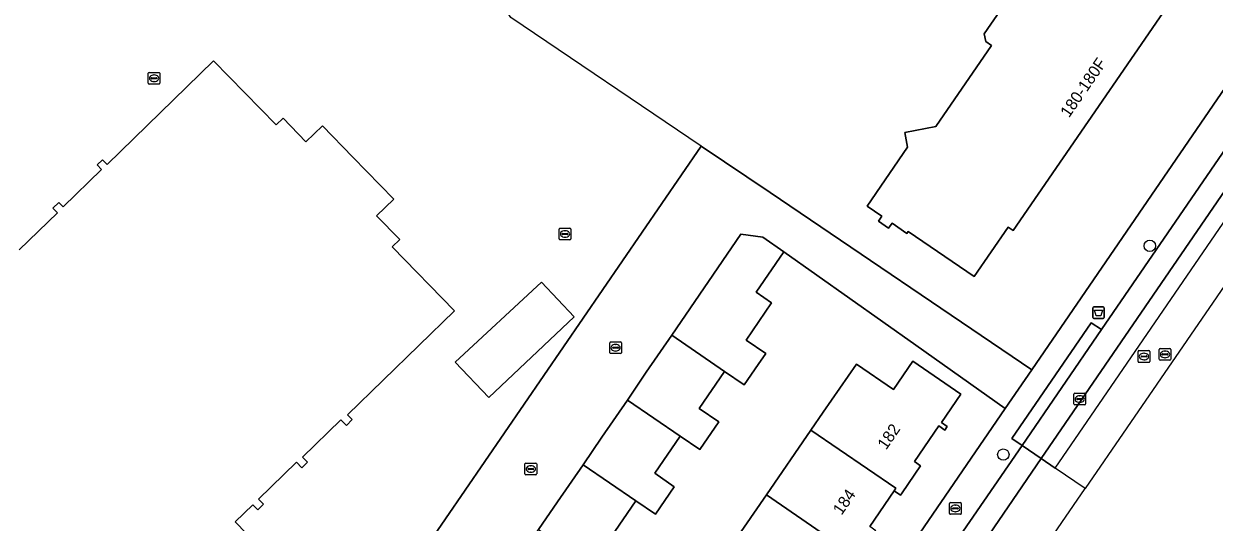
# Model space of a CAD drawing. Extents: x 159664 to 160323, y 385312 to 386115.
# Drawn here: x 160092.1 to 160193.9, y 385542.9 to 385585.5 of the extents above; entities that cross this region are included whole.
import ezdxf

# ---------------------------------------------------------------- set-up
doc = ezdxf.new("R2010")
doc.units = 0
for name, color, linetype in [('IMGEO_Afvalbak', 7, 'Continuous'), ('IMGEO_Boom', 7, 'Continuous'), ('IMGEO_Brandkraan', 7, 'Continuous'), ('IMGEO_Erf', 7, 'Continuous'), ('IMGEO_Hek', 7, 'Continuous'), ('IMGEO_Kolk', 7, 'Continuous'), ('IMGEO_Muur', 7, 'Continuous'), ('IMGEO_Pand', 7, 'Continuous'), ('IMGEO_Pand_nummerreeks', 7, 'Continuous'), ('IMGEO_Parkeervlak_open', 7, 'Continuous'), ('IMGEO_Rijbaan_lokaal_gesloten', 7, 'Continuous'), ('IMGEO_Rijbaan_lokaal_open', 7, 'Continuous'), ('IMGEO_Rioolput', 7, 'Continuous'), ('IMGEO_Voetpad_open', 7, 'Continuous')]:
    doc.layers.add(name, color=color, linetype=linetype)

msp = doc.modelspace()

# ---------------------------------------------------------------- linework, layer by layer
at = {"layer": 'IMGEO_Afvalbak'}
for p, q in [((160183.47, 385560.44), (160183.47, 385561.24)), ((160183.47, 385561.24), (160183.47, 385560.44)), ((160183.57, 385561.34), (160184.36, 385561.34)), ((160184.36, 385561.34), (160183.57, 385561.34)), ((160184.46, 385561.24), (160184.46, 385560.44)), ((160184.46, 385560.44), (160184.46, 385561.24)), ((160184.36, 385560.34), (160183.57, 385560.34)), ((160183.57, 385560.34), (160184.36, 385560.34))]:
    msp.add_line(p, q, dxfattribs=at)
msp.add_lwpolyline([(160183.61, 385561.05), (160184.32, 385561.05), (160184.17, 385560.58), (160183.76, 385560.58), (160183.61, 385561.05)], dxfattribs=at)
for centre, start, end in [((160183.57, 385561.24), 90, 180), ((160183.57, 385561.24), 90, 180), ((160184.36, 385561.24), 0, 90), ((160184.36, 385561.24), 360, 90), ((160183.57, 385560.44), 180, 270), ((160183.57, 385560.44), 180, 270), ((160184.36, 385560.44), 270, 0), ((160184.36, 385560.44), 270, 0)]:
    msp.add_arc(centre, 0.1, start, end, dxfattribs=at)
at = {"layer": 'IMGEO_Boom'}
for centre in [(160188.35, 385566.56), (160175.83, 385548.7)]:
    msp.add_circle(centre, 0.489, dxfattribs=at)
at = {"layer": 'IMGEO_Brandkraan'}
for p, q in [((160171.23, 385543.67), (160171.23, 385544.53)), ((160171.31, 385544.6), (160172.16, 385544.6)), ((160171.72, 385544.38), (160171.75, 385544.38)), ((160172.23, 385544.53), (160172.23, 385543.67)), ((160172.16, 385543.6), (160171.31, 385543.6)), ((160171.49, 385544.09), (160171.49, 385544.11)), ((160171.53, 385544.14), (160171.93, 385544.14)), ((160171.93, 385544.06), (160171.53, 385544.06)), ((160171.74, 385543.82), (160171.72, 385543.82)), ((160171.98, 385544.11), (160171.98, 385544.09))]:
    msp.add_line(p, q, dxfattribs=at)
for points in [[(160171.23, 385543.67), (160171.23, 385544.53)], [(160171.31, 385544.6), (160172.16, 385544.6)], [(160172.23, 385544.53), (160172.23, 385543.67)], [(160172.16, 385543.6), (160171.31, 385543.6)]]:
    msp.add_lwpolyline(points, dxfattribs=at)
for centre, radius, start, end in [((160171.31, 385544.52), 0.0765, 91.552, 178.448), ((160171.31, 385544.52), 0.0765, 91.552, 178.448), ((160172.16, 385544.52), 0.0765, 1.552, 88.448), ((160172.16, 385544.52), 0.0765, 1.552, 88.448), ((160171.31, 385543.67), 0.0765, 181.552, 268.448), ((160171.31, 385543.67), 0.0765, 181.552, 268.448), ((160171.53, 385544.1), 0.0403, 85.8775, 175.7526), ((160171.53, 385544.09), 0.0366, 178.938, 274.7102), ((160171.94, 385544.1), 0.0386, 1.7309, 96.639), ((160171.93, 385544.1), 0.043, 264.8664, 352.4533), ((160172.16, 385543.67), 0.0765, 271.552, 358.448), ((160172.16, 385543.67), 0.0765, 271.552, 358.448)]:
    msp.add_arc(centre, radius, start, end, dxfattribs=at)
for centre, major_axis, ratio, start_param, end_param in [((160171.72, 385544.1), (-0.387, 0.002), 0.722429, 4.712389, 7.853982), ((160171.74, 385544.1), (-0.39, 0.002), 0.717154, 1.570796, 4.712389)]:
    msp.add_ellipse(centre, major_axis=major_axis, ratio=ratio, start_param=start_param, end_param=end_param, dxfattribs=at)
at = {"layer": 'IMGEO_Erf'}
for points in [[(160193.45, 385592.29), (160176.67, 385567.86), (160176.24, 385568.16), (160173.33, 385563.92), (160167.71, 385567.78), (160167.59, 385567.61), (160166.32, 385568.48), (160166.03, 385568.07), (160165.15, 385568.67), (160165.45, 385569.1), (160164.2, 385569.96), (160167.65, 385574.99), (160167.42, 385576.26), (160170.06, 385576.75), (160174.82, 385583.68), (160174.33, 385584.02), (160174.2, 385584.68), (160175.6, 385586.72)], [(160126.47, 385540.77), (160150.01, 385575.09), (160155.89, 385571.12), (160178.27, 385555.96), (160202.57, 385591.48)], [(160091.73, 385566.22), (160094.98, 385569.39), (160094.6, 385569.78), (160095.11, 385570.27), (160095.48, 385569.89), (160098.76, 385573.08), (160098.39, 385573.47), (160098.84, 385573.91), (160099.23, 385573.51), (160108.33, 385582.37), (160113.67, 385576.89), (160114.27, 385577.47), (160116.23, 385575.46), (160117.63, 385576.82), (160120.24, 385574.14), (160123.73, 385570.55), (160122.26, 385569.12), (160124.24, 385567.09), (160123.6, 385566.47), (160128.92, 385561.01), (160119.79, 385552.11), (160120.19, 385551.7), (160119.68, 385551.2), (160119.22, 385551.67), (160115.93, 385548.48), (160116.36, 385548.04), (160115.89, 385547.57), (160115.41, 385548.05), (160112.17, 385544.9), (160112.61, 385544.45), (160112.11, 385543.97), (160111.68, 385544.41), (160110.18, 385542.95), (160111.14, 385541.96)], [(160149.71, 385514.25), (160176, 385552.63), (160168.35, 385558.05), (160157.07, 385566.03), (160154.72, 385562.6), (160156.03, 385561.69), (160153.85, 385558.5), (160155.52, 385557.36), (160154.89, 385556.42), (160153.68, 385554.67), (160152.01, 385555.82), (160149.84, 385552.64), (160151.51, 385551.5), (160149.89, 385549.13), (160148.22, 385550.28), (160146.04, 385547.1), (160147.71, 385545.95), (160146.1, 385543.6), (160144.43, 385544.74), (160142.26, 385541.57)], [(160151.77, 385539.72), (160155.58, 385545.25), (160159.38, 385550.78), (160160.44, 385552.32), (160163.27, 385556.44), (160166.45, 385554.27), (160168.09, 385556.68), (160172.21, 385553.87), (160170.55, 385551.44), (160171.04, 385551.11), (160170.83, 385550.8), (160170.31, 385551.15), (160168.23, 385548.1), (160168.76, 385547.74), (160167.19, 385545.43), (160167.05, 385545.23), (160166.49, 385545.6), (160164.41, 385542.54)]]:
    msp.add_lwpolyline(points, dxfattribs=at)
msp.add_lwpolyline([(160139.15, 385560.48), (160131.85, 385553.59), (160128.99, 385556.61), (160136.37, 385563.46)], close=True, dxfattribs=at)
at = {"layer": 'IMGEO_Hek'}
msp.add_lwpolyline([(160150.01, 385575.09), (160133.75, 385586.07), (160123.11, 385602.19), (160118.66, 385599.55), (160118.08, 385600.49)], dxfattribs=at)
at = {"layer": 'IMGEO_Kolk'}
for p, q in [((160142.19, 385557.41), (160142.19, 385558.27)), ((160142.27, 385558.34), (160143.12, 385558.34)), ((160142.45, 385557.83), (160142.45, 385557.85)), ((160142.49, 385557.88), (160142.89, 385557.88)), ((160142.89, 385557.8), (160142.49, 385557.8)), ((160142.68, 385558.12), (160142.71, 385558.12)), ((160142.94, 385557.85), (160142.94, 385557.83)), ((160143.19, 385558.27), (160143.19, 385557.41)), ((160143.12, 385557.34), (160142.27, 385557.34)), ((160142.7, 385557.56), (160142.68, 385557.56)), ((160181.86, 385553.03), (160181.86, 385553.88)), ((160181.94, 385553.96), (160182.79, 385553.96)), ((160182.16, 385553.5), (160182.56, 385553.5)), ((160182.35, 385553.73), (160182.37, 385553.73)), ((160182.86, 385553.88), (160182.86, 385553.03)), ((160182.79, 385552.95), (160181.94, 385552.95)), ((160182.12, 385553.45), (160182.12, 385553.46)), ((160182.56, 385553.41), (160182.16, 385553.41)), ((160182.37, 385553.18), (160182.35, 385553.18)), ((160182.6, 385553.46), (160182.6, 385553.45)), ((160134.95, 385547.05), (160134.95, 385547.9)), ((160135.02, 385547.98), (160135.87, 385547.98)), ((160135.2, 385547.47), (160135.2, 385547.48)), ((160135.64, 385547.43), (160135.24, 385547.43)), ((160135.25, 385547.52), (160135.64, 385547.52)), ((160135.43, 385547.75), (160135.46, 385547.75)), ((160135.69, 385547.48), (160135.69, 385547.47)), ((160135.95, 385547.9), (160135.95, 385547.05)), ((160135.87, 385546.97), (160135.02, 385546.97)), ((160135.46, 385547.2), (160135.43, 385547.2))]:
    msp.add_line(p, q, dxfattribs=at)
for points in [[(160142.19, 385557.41), (160142.19, 385558.27)], [(160142.27, 385558.34), (160143.12, 385558.34)], [(160143.19, 385558.27), (160143.19, 385557.41)], [(160143.12, 385557.34), (160142.27, 385557.34)], [(160181.86, 385553.03), (160181.86, 385553.88)], [(160181.94, 385553.96), (160182.79, 385553.96)], [(160182.86, 385553.88), (160182.86, 385553.03)], [(160182.79, 385552.95), (160181.94, 385552.95)], [(160134.95, 385547.05), (160134.95, 385547.9)], [(160135.02, 385547.98), (160135.87, 385547.98)], [(160135.95, 385547.9), (160135.95, 385547.05)], [(160135.87, 385546.97), (160135.02, 385546.97)]]:
    msp.add_lwpolyline(points, dxfattribs=at)
for centre, radius, start, end in [((160142.27, 385558.27), 0.0765, 91.552, 178.448), ((160142.27, 385558.27), 0.0765, 91.552, 178.448), ((160142.49, 385557.84), 0.0403, 85.8775, 175.7526), ((160142.49, 385557.83), 0.0366, 178.938, 274.7102), ((160142.9, 385557.85), 0.0386, 1.7309, 96.639), ((160142.89, 385557.84), 0.043, 264.8664, 352.4533), ((160143.12, 385558.27), 0.0765, 1.552, 88.448), ((160143.12, 385558.27), 0.0765, 1.552, 88.448), ((160142.27, 385557.42), 0.0765, 181.552, 268.448), ((160142.27, 385557.42), 0.0765, 181.552, 268.448), ((160143.12, 385557.42), 0.0765, 271.552, 358.448), ((160143.12, 385557.42), 0.0765, 271.552, 358.448), ((160181.94, 385553.88), 0.0765, 91.552, 178.448), ((160181.94, 385553.88), 0.0765, 91.552, 178.448), ((160182.16, 385553.46), 0.0403, 85.8775, 175.7526), ((160182.57, 385553.46), 0.0386, 1.7309, 96.639), ((160182.79, 385553.88), 0.0765, 1.552, 88.448), ((160182.79, 385553.88), 0.0765, 1.552, 88.448), ((160181.94, 385553.03), 0.0765, 181.552, 268.448), ((160181.94, 385553.03), 0.0765, 181.552, 268.448), ((160182.16, 385553.45), 0.0366, 178.938, 274.7102), ((160182.56, 385553.45), 0.043, 264.8664, 352.4533), ((160182.79, 385553.03), 0.0765, 271.552, 358.448), ((160182.79, 385553.03), 0.0765, 271.552, 358.448), ((160135.02, 385547.9), 0.0765, 91.552, 178.448), ((160135.02, 385547.9), 0.0765, 91.552, 178.448), ((160135.24, 385547.48), 0.0403, 85.8775, 175.7526), ((160135.24, 385547.47), 0.0366, 178.938, 274.7102), ((160135.65, 385547.48), 0.0386, 1.7309, 96.639), ((160135.65, 385547.47), 0.043, 264.8664, 352.4533), ((160135.87, 385547.9), 0.0765, 1.552, 88.448), ((160135.87, 385547.9), 0.0765, 1.552, 88.448), ((160135.02, 385547.05), 0.0765, 181.552, 268.448), ((160135.02, 385547.05), 0.0765, 181.552, 268.448), ((160135.87, 385547.05), 0.0765, 271.552, 358.448), ((160135.87, 385547.05), 0.0765, 271.552, 358.448)]:
    msp.add_arc(centre, radius, start, end, dxfattribs=at)
for centre, major_axis, ratio, start_param, end_param in [((160142.68, 385557.84), (-0.387, 0.002), 0.722429, 4.712389, 7.853982), ((160142.7, 385557.84), (-0.39, 0.002), 0.717154, 1.570796, 4.712389), ((160182.35, 385553.45), (-0.387, 0.002), 0.722429, 4.712389, 7.853982), ((160182.37, 385553.45), (-0.39, 0.002), 0.717154, 1.570796, 4.712389), ((160135.43, 385547.47), (-0.387, 0.002), 0.722429, 4.712389, 7.853982), ((160135.46, 385547.47), (-0.39, 0.002), 0.717154, 1.570796, 4.712389)]:
    msp.add_ellipse(centre, major_axis=major_axis, ratio=ratio, start_param=start_param, end_param=end_param, dxfattribs=at)
at = {"layer": 'IMGEO_Muur'}
msp.add_lwpolyline([(160168.35, 385558.05), (160157.07, 385566.03)], dxfattribs=at)
at = {"layer": 'IMGEO_Pand'}
for points in [[(160175.6, 385586.72), (160174.2, 385584.68), (160174.33, 385584.02), (160174.82, 385583.68), (160170.06, 385576.75), (160167.42, 385576.26), (160167.65, 385574.99), (160164.2, 385569.96), (160165.45, 385569.1), (160165.15, 385568.67), (160166.03, 385568.07), (160166.32, 385568.48), (160167.59, 385567.61), (160167.71, 385567.78), (160173.33, 385563.92), (160176.24, 385568.16), (160176.67, 385567.86), (160193.45, 385592.29)], [(160111.14, 385541.96), (160110.18, 385542.95), (160111.68, 385544.41), (160112.11, 385543.97), (160112.61, 385544.45), (160112.17, 385544.9), (160115.41, 385548.05), (160115.89, 385547.57), (160116.36, 385548.04), (160115.93, 385548.48), (160119.22, 385551.67), (160119.68, 385551.2), (160120.19, 385551.7), (160119.79, 385552.11), (160128.92, 385561.01), (160123.6, 385566.47), (160124.24, 385567.09), (160122.26, 385569.12), (160123.73, 385570.55), (160120.24, 385574.14), (160117.63, 385576.82), (160116.23, 385575.46), (160114.27, 385577.47), (160113.67, 385576.89), (160108.33, 385582.37), (160099.23, 385573.51), (160098.84, 385573.91), (160098.39, 385573.47), (160098.76, 385573.08), (160095.48, 385569.89), (160095.11, 385570.27), (160094.6, 385569.78), (160094.98, 385569.39), (160091.73, 385566.22)]]:
    msp.add_lwpolyline(points, dxfattribs=at)
for points in [[(160154.72, 385562.6), (160157.07, 385566.03), (160155.28, 385567.3), (160153.4, 385567.55), (160147.49, 385558.91), (160152.01, 385555.82), (160153.68, 385554.67), (160154.89, 385556.42), (160155.52, 385557.36), (160153.85, 385558.5), (160156.03, 385561.69)], [(160139.15, 385560.48), (160136.37, 385563.46), (160128.99, 385556.61), (160131.85, 385553.59)], [(160152.01, 385555.82), (160147.49, 385558.91), (160145.32, 385555.74), (160143.7, 385553.37), (160148.22, 385550.28), (160149.89, 385549.13), (160151.51, 385551.5), (160149.84, 385552.64)], [(160172.21, 385553.87), (160168.09, 385556.68), (160166.45, 385554.27), (160163.27, 385556.44), (160160.44, 385552.32), (160159.38, 385550.78), (160166.64, 385545.82), (160166.49, 385545.6), (160167.05, 385545.23), (160167.19, 385545.43), (160168.76, 385547.74), (160168.23, 385548.1), (160170.31, 385551.15), (160170.83, 385550.8), (160171.04, 385551.11), (160170.55, 385551.44)], [(160148.22, 385550.28), (160143.7, 385553.37), (160141.52, 385550.19), (160139.91, 385547.83), (160144.43, 385544.74), (160146.1, 385543.6), (160147.71, 385545.95), (160146.04, 385547.1)], [(160159.38, 385550.78), (160155.58, 385545.25), (160162.84, 385540.28), (160162.72, 385540.1), (160163.26, 385539.73), (160163.39, 385539.91), (160164.93, 385542.18), (160164.41, 385542.54), (160166.49, 385545.6), (160166.64, 385545.82)], [(160144.43, 385544.74), (160139.91, 385547.83), (160137.74, 385544.67), (160136.11, 385542.29), (160140.64, 385539.2), (160142.31, 385538.06), (160143.93, 385540.42), (160142.26, 385541.57)], [(160155.58, 385545.25), (160151.77, 385539.72), (160159.09, 385534.72), (160158.98, 385534.56), (160159.51, 385534.2), (160159.62, 385534.35), (160161.18, 385536.64), (160160.62, 385537.02), (160162.72, 385540.1), (160162.84, 385540.28)]]:
    msp.add_lwpolyline(points, close=True, dxfattribs=at)
at = {"layer": 'IMGEO_Parkeervlak_open'}
for points in [[(160179.07, 385548.37), (160214.31, 385599.82)], [(160203.92, 385588.15), (160184.21, 385559.4)], [(160184.21, 385559.4), (160177.43, 385549.49)], [(160177.43, 385549.49), (160179.07, 385548.37)]]:
    msp.add_lwpolyline(points, dxfattribs=at)
msp.add_lwpolyline([(160171.77, 385541.23), (160173.43, 385540.1), (160179.07, 385548.37), (160177.43, 385549.49)], close=True, dxfattribs=at)
at = {"layer": 'IMGEO_Rijbaan_lokaal_gesloten'}
for points in [[(160232.59, 385623.94), (160231.37, 385624.76), (160215.29, 385601.23), (160215.23, 385601.14), (160214.31, 385599.82), (160179.07, 385548.37), (160180.26, 385547.55)], [(160182.82, 385545.79), (160180.26, 385547.55), (160232.59, 385623.94), (160235.22, 385622.16), (160233.16, 385619.15), (160186.38, 385550.98)]]:
    msp.add_lwpolyline(points, close=True, dxfattribs=at)
at = {"layer": 'IMGEO_Rijbaan_lokaal_open'}
for points in [[(160139.91, 385547.83), (160141.52, 385550.19), (160143.7, 385553.37), (160145.32, 385555.74), (160147.49, 385558.91), (160153.4, 385567.55), (160155.28, 385567.3), (160157.07, 385566.03), (160168.35, 385558.05), (160176, 385552.63), (160177.7, 385555.13), (160178.27, 385555.96), (160155.89, 385571.12), (160150.01, 385575.09), (160126.47, 385540.77), (160132.33, 385536.76), (160133.93, 385539.11), (160136.11, 385542.29), (160137.74, 385544.67)], [(160177.15, 385537.53), (160182.82, 385545.79), (160180.26, 385547.55), (160179.07, 385548.37), (160173.43, 385540.1), (160174.59, 385539.29)]]:
    msp.add_lwpolyline(points, close=True, dxfattribs=at)
at = {"layer": 'IMGEO_Rioolput'}
for p, q in [((160102.75, 385580.46), (160102.75, 385581.32)), ((160102.82, 385581.39), (160103.68, 385581.39)), ((160103.24, 385581.17), (160103.26, 385581.17)), ((160103.75, 385581.32), (160103.75, 385580.46)), ((160103.68, 385580.39), (160102.82, 385580.39)), ((160103.01, 385580.88), (160103.01, 385580.9)), ((160103.05, 385580.93), (160103.45, 385580.93)), ((160103.44, 385580.85), (160103.05, 385580.85)), ((160103.26, 385580.61), (160103.23, 385580.61)), ((160103.49, 385580.9), (160103.49, 385580.88)), ((160137.87, 385567.14), (160137.87, 385568)), ((160137.94, 385568.07), (160138.8, 385568.07)), ((160138.36, 385567.85), (160138.38, 385567.85)), ((160138.87, 385568), (160138.87, 385567.14)), ((160138.8, 385567.07), (160137.94, 385567.07)), ((160138.13, 385567.56), (160138.13, 385567.58)), ((160138.17, 385567.61), (160138.57, 385567.61)), ((160138.56, 385567.53), (160138.17, 385567.53)), ((160138.38, 385567.29), (160138.35, 385567.29)), ((160138.61, 385567.58), (160138.61, 385567.56)), ((160187.42, 385557.59), (160188.28, 385557.59)), ((160189.15, 385556.85), (160189.15, 385557.7)), ((160189.22, 385557.77), (160190.08, 385557.77)), ((160190.15, 385557.7), (160190.15, 385556.85)), ((160187.35, 385556.66), (160187.35, 385557.52)), ((160188.28, 385556.59), (160187.42, 385556.59)), ((160187.61, 385557.08), (160187.61, 385557.1)), ((160187.65, 385557.13), (160188.05, 385557.13)), ((160188.04, 385557.05), (160187.65, 385557.05)), ((160187.86, 385556.81), (160187.83, 385556.81)), ((160187.84, 385557.37), (160187.86, 385557.37)), ((160188.09, 385557.1), (160188.09, 385557.08)), ((160188.35, 385557.52), (160188.35, 385556.66)), ((160190.08, 385556.77), (160189.22, 385556.77)), ((160189.41, 385557.27), (160189.41, 385557.28)), ((160189.45, 385557.32), (160189.85, 385557.32)), ((160189.85, 385557.23), (160189.45, 385557.23)), ((160189.64, 385557.55), (160189.66, 385557.55)), ((160189.66, 385556.99), (160189.64, 385556.99)), ((160189.89, 385557.28), (160189.89, 385557.27))]:
    msp.add_line(p, q, dxfattribs=at)
for points in [[(160102.75, 385580.46), (160102.75, 385581.32)], [(160102.82, 385581.39), (160103.68, 385581.39)], [(160103.75, 385581.32), (160103.75, 385580.46)], [(160103.68, 385580.39), (160102.82, 385580.39)], [(160137.87, 385567.14), (160137.87, 385568)], [(160137.94, 385568.07), (160138.8, 385568.07)], [(160138.87, 385568), (160138.87, 385567.14)], [(160138.8, 385567.07), (160137.94, 385567.07)], [(160187.42, 385557.59), (160188.28, 385557.59)], [(160189.15, 385556.85), (160189.15, 385557.7)], [(160189.22, 385557.77), (160190.08, 385557.77)], [(160190.15, 385557.7), (160190.15, 385556.85)], [(160187.35, 385556.66), (160187.35, 385557.52)], [(160188.28, 385556.59), (160187.42, 385556.59)], [(160188.35, 385557.52), (160188.35, 385556.66)], [(160190.08, 385556.77), (160189.22, 385556.77)]]:
    msp.add_lwpolyline(points, dxfattribs=at)
for centre, radius, start, end in [((160102.82, 385581.31), 0.0765, 91.552, 178.448), ((160102.82, 385581.31), 0.0765, 91.552, 178.448), ((160103.67, 385581.31), 0.0765, 1.552, 88.448), ((160103.67, 385581.31), 0.0765, 1.552, 88.448), ((160102.82, 385580.47), 0.0765, 181.552, 268.448), ((160102.82, 385580.47), 0.0765, 181.552, 268.448), ((160103.05, 385580.89), 0.0403, 85.8775, 175.7526), ((160103.04, 385580.88), 0.0366, 178.938, 274.7102), ((160103.45, 385580.89), 0.043, 264.8664, 352.4533), ((160103.45, 385580.89), 0.0386, 1.7309, 96.639), ((160103.67, 385580.47), 0.0765, 271.552, 358.448), ((160103.67, 385580.47), 0.0765, 271.552, 358.448), ((160137.94, 385567.99), 0.0765, 91.552, 178.448), ((160137.94, 385567.99), 0.0765, 91.552, 178.448), ((160138.79, 385567.99), 0.0765, 1.552, 88.448), ((160138.79, 385567.99), 0.0765, 1.552, 88.448), ((160137.94, 385567.15), 0.0765, 181.552, 268.448), ((160137.94, 385567.15), 0.0765, 181.552, 268.448), ((160138.17, 385567.57), 0.0403, 85.8775, 175.7526), ((160138.16, 385567.56), 0.0366, 178.938, 274.7102), ((160138.57, 385567.57), 0.043, 264.8664, 352.4533), ((160138.57, 385567.57), 0.0386, 1.7309, 96.639), ((160138.79, 385567.15), 0.0765, 271.552, 358.448), ((160138.79, 385567.15), 0.0765, 271.552, 358.448), ((160187.42, 385557.52), 0.0765, 91.552, 178.448), ((160187.42, 385557.52), 0.0765, 91.552, 178.448), ((160188.27, 385557.52), 0.0765, 1.552, 88.448), ((160188.27, 385557.52), 0.0765, 1.552, 88.448), ((160189.23, 385557.7), 0.0765, 91.552, 178.448), ((160189.23, 385557.7), 0.0765, 91.552, 178.448), ((160190.07, 385557.7), 0.0765, 1.552, 88.448), ((160190.07, 385557.7), 0.0765, 1.552, 88.448), ((160187.42, 385556.67), 0.0765, 181.552, 268.448), ((160187.42, 385556.67), 0.0765, 181.552, 268.448), ((160187.65, 385557.09), 0.0403, 85.8775, 175.7526), ((160187.64, 385557.08), 0.0366, 178.938, 274.7102), ((160188.05, 385557.09), 0.043, 264.8664, 352.4533), ((160188.05, 385557.1), 0.0386, 1.7309, 96.639), ((160188.27, 385556.67), 0.0765, 271.552, 358.448), ((160188.27, 385556.67), 0.0765, 271.552, 358.448), ((160189.23, 385556.85), 0.0765, 181.552, 268.448), ((160189.23, 385556.85), 0.0765, 181.552, 268.448), ((160189.45, 385557.28), 0.0403, 85.8775, 175.7526), ((160189.45, 385557.27), 0.0366, 178.938, 274.7102), ((160189.85, 385557.28), 0.0386, 1.7309, 96.639), ((160189.85, 385557.27), 0.043, 264.8664, 352.4533), ((160190.07, 385556.85), 0.0765, 271.552, 358.448), ((160190.07, 385556.85), 0.0765, 271.552, 358.448)]:
    msp.add_arc(centre, radius, start, end, dxfattribs=at)
for centre, major_axis, ratio, start_param, end_param in [((160103.24, 385580.89), (-0.387, 0.002), 0.722429, 4.712389, 7.853982), ((160103.26, 385580.89), (-0.39, 0.002), 0.717154, 1.570796, 4.712389), ((160138.36, 385567.57), (-0.387, 0.002), 0.722429, 4.712389, 7.853982), ((160138.38, 385567.57), (-0.39, 0.002), 0.717154, 1.570796, 4.712389), ((160187.84, 385557.09), (-0.387, 0.002), 0.722429, 4.712389, 7.853982), ((160187.86, 385557.09), (-0.39, 0.002), 0.717154, 1.570796, 4.712389), ((160189.64, 385557.27), (-0.387, 0.002), 0.722429, 4.712389, 7.853982), ((160189.66, 385557.27), (-0.39, 0.002), 0.717154, 1.570796, 4.712389)]:
    msp.add_ellipse(centre, major_axis=major_axis, ratio=ratio, start_param=start_param, end_param=end_param, dxfattribs=at)
at = {"layer": 'IMGEO_Voetpad_open'}
for points in [[(160245.33, 385653.94), (160242.86, 385650.38), (160232.68, 385635.5), (160232.18, 385634.76), (160232.1, 385634.65), (160228.78, 385629.78), (160204.8, 385594.74), (160202.57, 385591.48), (160178.27, 385555.96), (160177.7, 385555.13), (160176, 385552.63), (160149.71, 385514.25), (160148.99, 385513.2), (160142.13, 385503.18), (160129.76, 385485.1), (160128.19, 385482.81)], [(160171.77, 385541.23), (160177.43, 385549.49), (160176.55, 385550.07), (160183.34, 385559.98), (160184.21, 385559.4), (160203.92, 385588.15), (160203.06, 385588.75), (160207.23, 385594.83), (160208.09, 385594.24), (160210.8, 385598.21)]]:
    msp.add_lwpolyline(points, dxfattribs=at)
msp.add_lwpolyline([(160177.43, 385549.49), (160184.21, 385559.4), (160183.34, 385559.98), (160176.55, 385550.07)], close=True, dxfattribs=at)

# ---------------------------------------------------------------- texts
at = {"layer": 'IMGEO_Pand_nummerreeks'}
for s, rotation, p in [('180-180F', 55.5253, (160181.45, 385577.46)), ('182', 55.703, (160165.82, 385549.05)), ('184', 55.703, (160162.01, 385543.46))]:
    msp.add_text(s, height=1, rotation=rotation, dxfattribs=at).set_placement(p)

doc.saveas('drawing.dxf')
